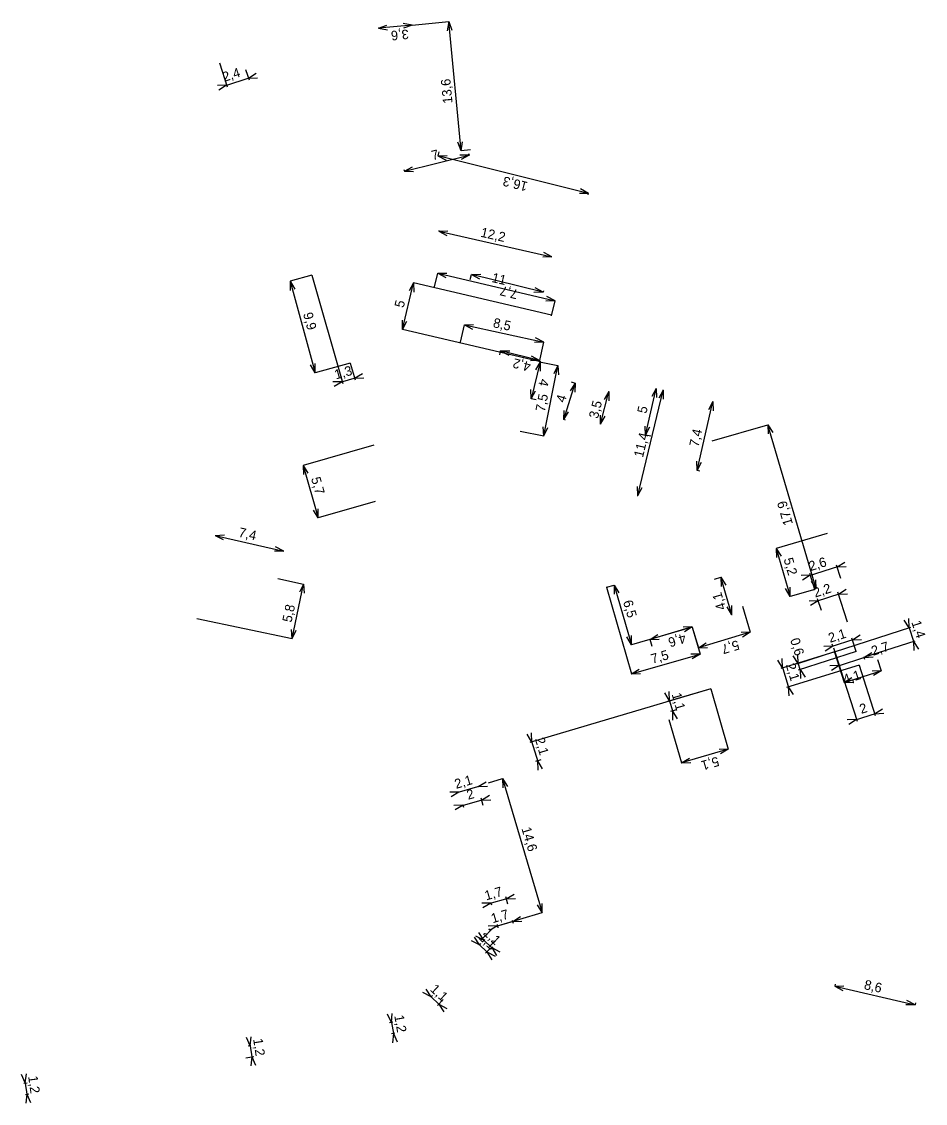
# Model space of a CAD drawing. Extents: x -743226 to -743024, y -1051383 to -1051228.
# Drawn here: x -743118.3 to -743023.7, y -1051341.7 to -1051228.4 of the extents above; entities that cross this region are included whole.
import ezdxf

# ---------------------------------------------------------------- set-up
doc = ezdxf.new("R2010")
doc.units = 0
doc.layers.add('Kota_NN', color=7, linetype='Continuous')
doc.layers.add('Kota_VN', color=7, linetype='Continuous')

msp = doc.modelspace()

# ---------------------------------------------------------------- linework, layer by layer
at = {"layer": 'Kota_NN'}
for p, q in [((-743097.59, -1051232.76), (-743096.78, -1051235.29)), ((-743094.86, -1051233.45), (-743094.5, -1051234.56)), ((-743094.56, -1051234.37), (-743093.75, -1051233.85)), ((-743096.84, -1051235.1), (-743097.8, -1051235.14)), ((-743096.84, -1051235.1), (-743097.65, -1051235.62)), ((-743097.03, -1051235.16), (-743094.37, -1051234.31)), ((-743094.56, -1051234.37), (-743093.6, -1051234.32)), ((-743078.23, -1051244.12), (-743071.47, -1051242.44)), ((-743071.47, -1051242.44), (-743072.43, -1051242.42)), ((-743071.47, -1051242.44), (-743072.31, -1051242.9)), ((-743071.52, -1051242.24), (-743071.47, -1051242.44)), ((-743078.28, -1051243.92), (-743078.23, -1051244.12)), ((-743078.23, -1051244.12), (-743077.39, -1051243.65)), ((-743078.23, -1051244.12), (-743077.27, -1051244.14)), ((-743087.92, -1051255.01), (-743090.19, -1051255.63)), ((-743087.92, -1051255.01), (-743084.69, -1051266.34)), ((-743075.07, -1051256.22), (-743074.74, -1051254.8)), ((-743074.74, -1051254.8), (-743073.78, -1051254.77)), ((-743074.74, -1051254.8), (-743062.47, -1051257.68)), ((-743074.74, -1051254.8), (-743073.89, -1051255.25)), ((-743090.19, -1051255.63), (-743087.58, -1051265.22)), ((-743090.19, -1051255.63), (-743089.71, -1051256.46)), ((-743090.19, -1051255.63), (-743090.18, -1051256.59)), ((-743078.42, -1051260.68), (-743077.28, -1051255.8)), ((-743077.28, -1051255.8), (-743077.73, -1051256.65)), ((-743062.83, -1051259.19), (-743077.28, -1051255.8)), ((-743077.28, -1051255.8), (-743077.25, -1051256.76)), ((-743062.47, -1051257.68), (-743063.43, -1051257.71)), ((-743062.47, -1051257.68), (-743063.32, -1051257.22)), ((-743062.84, -1051259.26), (-743062.47, -1051257.68)), ((-743078.42, -1051260.68), (-743078.45, -1051259.72)), ((-743078.42, -1051260.68), (-743077.97, -1051259.83)), ((-743063.97, -1051264.07), (-743078.42, -1051260.68)), ((-743072.35, -1051262.01), (-743071.96, -1051260.2)), ((-743071.96, -1051260.2), (-743071, -1051260.15)), ((-743071.96, -1051260.2), (-743063.65, -1051262.01)), ((-743071.96, -1051260.2), (-743071.11, -1051260.64)), ((-743063.65, -1051262.01), (-743064.61, -1051262.06)), ((-743063.65, -1051262.01), (-743064.5, -1051261.57)), ((-743064.1, -1051264.07), (-743063.65, -1051262.01)), ((-743087.58, -1051265.22), (-743088.06, -1051264.39)), ((-743083.9, -1051264.22), (-743087.58, -1051265.22)), ((-743087.58, -1051265.22), (-743087.58, -1051264.26)), ((-743083.9, -1051264.22), (-743083.4, -1051265.97)), ((-743064.1, -1051264.07), (-743062.16, -1051264.46)), ((-743063.64, -1051271.82), (-743062.16, -1051264.46)), ((-743062.16, -1051264.46), (-743062.58, -1051265.32)), ((-743062.16, -1051264.46), (-743062.1, -1051265.42)), ((-743084.94, -1051266.2), (-743083.26, -1051265.72)), ((-743083.45, -1051265.78), (-743082.63, -1051265.29)), ((-743083.45, -1051265.78), (-743082.49, -1051265.76)), ((-743084.75, -1051266.15), (-743085.71, -1051266.16)), ((-743084.75, -1051266.15), (-743085.57, -1051266.64)), ((-743053.8, -1051278.08), (-743051.16, -1051267.03)), ((-743051.16, -1051267.03), (-743051.62, -1051267.87)), ((-743051.23, -1051267.01), (-743051.16, -1051267.03)), ((-743051.16, -1051267.03), (-743051.14, -1051267.99)), ((-743066.12, -1051271.32), (-743063.64, -1051271.82)), ((-743063.64, -1051271.82), (-743063.7, -1051270.87)), ((-743063.64, -1051271.82), (-743063.22, -1051270.96)), ((-743081.42, -1051272.8), (-743088.82, -1051274.91)), ((-743088.82, -1051274.91), (-743087.26, -1051280.41)), ((-743088.82, -1051274.91), (-743088.33, -1051275.74)), ((-743088.82, -1051274.91), (-743088.81, -1051275.87)), ((-743053.8, -1051278.08), (-743053.83, -1051277.12)), ((-743053.87, -1051278.06), (-743053.8, -1051278.08)), ((-743053.8, -1051278.08), (-743053.34, -1051277.24)), ((-743081.28, -1051278.7), (-743087.26, -1051280.41)), ((-743087.26, -1051280.41), (-743087.75, -1051279.59)), ((-743087.26, -1051280.41), (-743087.27, -1051279.45)), ((-743098.04, -1051282.24), (-743097.08, -1051282.2)), ((-743098.04, -1051282.24), (-743098.04, -1051282.24)), ((-743098.04, -1051282.24), (-743090.87, -1051283.88)), ((-743098.04, -1051282.24), (-743097.19, -1051282.69)), ((-743033.99, -1051282.05), (-743039.31, -1051283.6)), ((-743090.87, -1051283.88), (-743091.83, -1051283.91)), ((-743090.87, -1051283.88), (-743091.72, -1051283.43)), ((-743090.87, -1051283.88), (-743090.87, -1051283.88)), ((-743039.31, -1051283.6), (-743037.84, -1051288.64)), ((-743039.31, -1051283.6), (-743038.81, -1051284.42)), ((-743039.31, -1051283.6), (-743039.28, -1051284.56)), ((-743032.94, -1051285.54), (-743032.13, -1051285.03)), ((-743035.94, -1051286.48), (-743032.75, -1051285.48)), ((-743032.56, -1051286.75), (-743033, -1051285.35)), ((-743032.94, -1051285.54), (-743031.98, -1051285.5)), ((-743091.49, -1051286.77), (-743088.79, -1051287.34)), ((-743035.75, -1051286.42), (-743036.71, -1051286.46)), ((-743035.75, -1051286.42), (-743036.56, -1051286.93)), ((-743035.29, -1051287.9), (-743035.81, -1051286.23)), ((-743089.99, -1051293.04), (-743088.79, -1051287.34)), ((-743088.79, -1051287.34), (-743089.22, -1051288.2)), ((-743088.79, -1051287.34), (-743088.74, -1051288.3)), ((-743057.08, -1051287.67), (-743056.29, -1051287.44)), ((-743057.08, -1051287.67), (-743054.47, -1051296.74)), ((-743056.29, -1051287.44), (-743054.45, -1051293.7)), ((-743056.29, -1051287.44), (-743055.79, -1051288.26)), ((-743056.29, -1051287.44), (-743056.27, -1051288.4)), ((-743037.84, -1051288.64), (-743038.34, -1051287.82)), ((-743037.84, -1051288.64), (-743037.86, -1051287.68)), ((-743035.29, -1051287.9), (-743037.84, -1051288.64)), ((-743035.11, -1051289.14), (-743032.61, -1051288.33)), ((-743031.85, -1051291.34), (-743032.86, -1051288.2)), ((-743032.8, -1051288.39), (-743031.99, -1051287.87)), ((-743032.8, -1051288.39), (-743031.84, -1051288.35)), ((-743034.92, -1051289.08), (-743035.88, -1051289.12)), ((-743034.92, -1051289.08), (-743035.72, -1051289.6)), ((-743034.59, -1051290.1), (-743034.98, -1051288.89)), ((-743099.95, -1051290.95), (-743089.99, -1051293.04)), ((-743048.11, -1051291.84), (-743054.45, -1051293.7)), ((-743048.11, -1051291.84), (-743047.29, -1051294.68)), ((-743025.41, -1051291.92), (-743025.93, -1051291.11)), ((-743025.47, -1051291.73), (-743024.89, -1051293.53)), ((-743025.41, -1051291.92), (-743025.45, -1051290.96)), ((-743089.99, -1051293.04), (-743090.04, -1051292.08)), ((-743089.99, -1051293.04), (-743089.55, -1051292.18)), ((-743054.45, -1051293.7), (-743054.95, -1051292.88)), ((-743054.45, -1051293.7), (-743054.48, -1051292.74)), ((-743033.2, -1051294.43), (-743025.22, -1051291.86)), ((-743030.96, -1051294.39), (-743031.41, -1051292.99)), ((-743031.35, -1051293.18), (-743030.54, -1051292.65)), ((-743033.39, -1051293.83), (-743034.35, -1051293.88)), ((-743033.39, -1051293.83), (-743034.2, -1051294.35)), ((-743033.58, -1051293.89), (-743031.16, -1051293.11)), ((-743033.37, -1051293.9), (-743033.45, -1051293.64)), ((-743033.33, -1051294.03), (-743030.86, -1051301.71)), ((-743031.35, -1051293.18), (-743030.39, -1051293.13)), ((-743030.13, -1051295.01), (-743024.76, -1051293.28)), ((-743024.95, -1051293.34), (-743024.43, -1051294.15)), ((-743024.95, -1051293.34), (-743024.9, -1051294.3)), ((-743054.47, -1051296.74), (-743047.29, -1051294.68)), ((-743047.29, -1051294.68), (-743048.25, -1051294.69)), ((-743047.29, -1051294.68), (-743048.12, -1051295.17)), ((-743033.18, -1051294.43), (-743038.85, -1051296.17)), ((-743038.66, -1051296.11), (-743038.69, -1051295.15)), ((-743037.02, -1051295.66), (-743037.54, -1051294.85)), ((-743033.2, -1051294.43), (-743037.21, -1051295.72)), ((-743037.02, -1051295.66), (-743037.07, -1051294.7)), ((-743030.96, -1051294.39), (-743037.01, -1051296.34)), ((-743033.25, -1051294.35), (-743032.19, -1051297.65)), ((-743033.22, -1051294.34), (-743032.67, -1051296.05)), ((-743032.92, -1051295.92), (-743029.94, -1051294.96)), ((-743030.13, -1051295.02), (-743029.32, -1051294.5)), ((-743030.13, -1051295.02), (-743029.17, -1051294.97)), ((-743030.13, -1051295.01), (-743030.07, -1051295.21)), ((-743028.7, -1051295.24), (-743028.33, -1051296.41)), ((-743054.47, -1051296.74), (-743053.65, -1051296.25)), ((-743038.66, -1051296.11), (-743039.16, -1051295.3)), ((-743038.71, -1051295.92), (-743037.99, -1051298.29)), ((-743030.64, -1051295.82), (-743038.24, -1051298.16)), ((-743037.08, -1051295.47), (-743036.76, -1051296.47)), ((-743036.82, -1051296.28), (-743036.3, -1051297.09)), ((-743036.82, -1051296.28), (-743036.77, -1051297.24)), ((-743032.73, -1051295.86), (-743033.69, -1051295.9)), ((-743032.73, -1051295.86), (-743033.54, -1051296.38)), ((-743030.65, -1051295.82), (-743028.95, -1051301.1)), ((-743054.47, -1051296.74), (-743053.51, -1051296.72)), ((-743032.19, -1051297.65), (-743028.33, -1051296.41)), ((-743032.19, -1051297.65), (-743031.39, -1051297.13)), ((-743028.33, -1051296.41), (-743029.29, -1051296.45)), ((-743028.33, -1051296.41), (-743029.14, -1051296.93)), ((-743038.05, -1051298.1), (-743037.54, -1051298.91)), ((-743038.05, -1051298.1), (-743038.01, -1051299.06)), ((-743032.19, -1051297.65), (-743031.23, -1051297.6)), ((-743031.11, -1051301.58), (-743028.83, -1051300.85)), ((-743029.02, -1051300.91), (-743028.21, -1051300.39)), ((-743029.02, -1051300.91), (-743028.06, -1051300.86)), ((-743030.92, -1051301.52), (-743031.88, -1051301.57)), ((-743030.92, -1051301.52), (-743031.73, -1051302.04)), ((-743069.42, -1051308.14), (-743067.96, -1051307.71)), ((-743067.96, -1051307.71), (-743063.81, -1051321.73)), ((-743067.96, -1051307.71), (-743067.46, -1051308.53)), ((-743067.96, -1051307.71), (-743067.94, -1051308.67)), ((-743072.72, -1051309.17), (-743070.31, -1051308.47)), ((-743070.5, -1051308.52), (-743069.68, -1051308.03)), ((-743070.5, -1051308.52), (-743069.54, -1051308.5)), ((-743070.5, -1051308.52), (-743070.5, -1051308.52)), ((-743072.53, -1051309.12), (-743073.49, -1051309.14)), ((-743072.53, -1051309.12), (-743073.35, -1051309.62)), ((-743072.53, -1051309.12), (-743072.53, -1051309.12)), ((-743063.81, -1051321.73), (-743064.31, -1051320.91)), ((-743063.81, -1051321.73), (-743063.83, -1051320.77)), ((-743068.5, -1051323.12), (-743063.81, -1051321.73)), ((-743066.89, -1051322.66), (-743066.07, -1051322.16)), ((-743068.5, -1051323.13), (-743069.46, -1051323.15)), ((-743068.5, -1051323.13), (-743069.32, -1051323.63)), ((-743068.69, -1051323.19), (-743066.7, -1051322.6)), ((-743068.54, -1051322.99), (-743068.44, -1051323.32)), ((-743066.94, -1051322.52), (-743066.84, -1051322.85)), ((-743066.89, -1051322.66), (-743065.93, -1051322.63)), ((-743069.92, -1051324.64), (-743070.77, -1051324.19)), ((-743069.92, -1051324.64), (-743070.43, -1051323.83)), ((-743070.07, -1051324.51), (-743068.95, -1051325.55)), ((-743069.83, -1051324.55), (-743070.06, -1051324.79)), ((-743069, -1051325.32), (-743069.23, -1051325.56)), ((-743069.09, -1051325.41), (-743068.24, -1051325.86)), ((-743069.09, -1051325.41), (-743068.58, -1051326.23)), ((-743033.14, -1051329.25), (-743033.19, -1051329.45)), ((-743033.19, -1051329.45), (-743032.23, -1051329.42)), ((-743033.19, -1051329.45), (-743024.78, -1051331.38)), ((-743033.19, -1051329.45), (-743032.34, -1051329.9)), ((-743024.78, -1051331.38), (-743025.74, -1051331.41)), ((-743024.78, -1051331.38), (-743025.63, -1051330.93)), ((-743024.73, -1051331.18), (-743024.78, -1051331.38)), ((-743079.59, -1051333.25), (-743079.99, -1051332.38)), ((-743079.59, -1051333.25), (-743079.5, -1051332.29)), ((-743079.44, -1051333.22), (-743079.78, -1051333.28)), ((-743079.62, -1051333.05), (-743079.35, -1051334.61)), ((-743079.23, -1051334.38), (-743079.58, -1051334.44)), ((-743079.38, -1051334.41), (-743079.47, -1051335.37)), ((-743079.38, -1051334.41), (-743078.98, -1051335.28)), ((-743117.92, -1051339.58), (-743118.3, -1051338.7)), ((-743117.95, -1051339.38), (-743117.73, -1051340.96)), ((-743117.92, -1051339.58), (-743117.8, -1051338.63)), ((-743118.07, -1051339.6), (-743117.72, -1051339.55)), ((-743117.91, -1051340.78), (-743117.56, -1051340.73)), ((-743117.76, -1051340.76), (-743117.87, -1051341.71)), ((-743117.76, -1051340.76), (-743117.38, -1051341.64))]:
    msp.add_line(p, q, dxfattribs=at)
at = {"layer": 'Kota_VN'}
for p, q in [((-743077.42, -1051228.81), (-743080.96, -1051229.15)), ((-743080.96, -1051229.15), (-743080.06, -1051228.82)), ((-743080.96, -1051229.15), (-743080.96, -1051229.15)), ((-743080.96, -1051229.15), (-743080.01, -1051229.31)), ((-743077.42, -1051228.81), (-743078.36, -1051228.66)), ((-743077.42, -1051228.81), (-743078.32, -1051229.15)), ((-743077.42, -1051228.81), (-743073.6, -1051228.45)), ((-743077.42, -1051228.81), (-743077.42, -1051228.81)), ((-743073.6, -1051228.45), (-743073.76, -1051229.4)), ((-743072.31, -1051241.99), (-743073.6, -1051228.45)), ((-743073.6, -1051228.45), (-743073.27, -1051229.35)), ((-743072.31, -1051241.99), (-743072.64, -1051241.08)), ((-743072.31, -1051241.99), (-743072.15, -1051241.04)), ((-743071.31, -1051241.89), (-743072.31, -1051241.99)), ((-743074.62, -1051242.08), (-743074.72, -1051242.49)), ((-743074.72, -1051242.49), (-743073.76, -1051242.47)), ((-743058.95, -1051246.44), (-743074.72, -1051242.49)), ((-743074.72, -1051242.49), (-743073.88, -1051242.96)), ((-743058.95, -1051246.44), (-743059.91, -1051246.45)), ((-743058.95, -1051246.44), (-743059.79, -1051245.97)), ((-743058.99, -1051246.6), (-743058.95, -1051246.44)), ((-743074.63, -1051250.32), (-743074.64, -1051250.4)), ((-743074.64, -1051250.4), (-743073.68, -1051250.36)), ((-743074.64, -1051250.4), (-743062.79, -1051253.07)), ((-743074.64, -1051250.4), (-743073.79, -1051250.84)), ((-743062.79, -1051253.07), (-743063.75, -1051253.11)), ((-743062.79, -1051253.07), (-743063.64, -1051252.62)), ((-743062.79, -1051253.07), (-743062.79, -1051253.07)), ((-743071.34, -1051255.45), (-743071.2, -1051254.92)), ((-743071.2, -1051254.92), (-743070.24, -1051254.9)), ((-743063.71, -1051256.79), (-743071.2, -1051254.92)), ((-743071.2, -1051254.92), (-743070.37, -1051255.38)), ((-743063.71, -1051256.79), (-743064.55, -1051256.32)), ((-743063.68, -1051256.65), (-743063.71, -1051256.79)), ((-743063.71, -1051256.79), (-743064.68, -1051256.81)), ((-743068.26, -1051263.34), (-743068.16, -1051262.92)), ((-743068.16, -1051262.92), (-743067.2, -1051262.91)), ((-743064.09, -1051263.94), (-743068.16, -1051262.92)), ((-743068.16, -1051262.92), (-743067.32, -1051263.39)), ((-743064.09, -1051263.94), (-743064.93, -1051263.47)), ((-743064.09, -1051263.94), (-743065.05, -1051263.95)), ((-743064.04, -1051264.08), (-743064.98, -1051267.93)), ((-743064.04, -1051264.08), (-743064.5, -1051264.92)), ((-743064.09, -1051263.93), (-743064.09, -1051263.94)), ((-743064.03, -1051264.08), (-743064.04, -1051264.08)), ((-743064.04, -1051264.08), (-743064.02, -1051265.04)), ((-743061.56, -1051270.12), (-743060.36, -1051266.29)), ((-743060.36, -1051266.29), (-743060.88, -1051267.1)), ((-743060.78, -1051266.16), (-743060.36, -1051266.29)), ((-743060.36, -1051266.29), (-743060.4, -1051267.25)), ((-743053, -1051271.75), (-743051.9, -1051266.85)), ((-743051.9, -1051266.85), (-743052.35, -1051267.71)), ((-743051.9, -1051266.85), (-743051.9, -1051266.85)), ((-743051.9, -1051266.85), (-743051.86, -1051267.81)), ((-743064.98, -1051267.93), (-743065, -1051266.97)), ((-743064.98, -1051267.93), (-743064.52, -1051267.09)), ((-743064.45, -1051268.06), (-743064.98, -1051267.93)), ((-743057.7, -1051270.6), (-743056.85, -1051267.18)), ((-743056.85, -1051267.18), (-743057.31, -1051268.02)), ((-743056.86, -1051267.18), (-743056.85, -1051267.18)), ((-743056.85, -1051267.18), (-743056.83, -1051268.14)), ((-743061.56, -1051270.12), (-743061.52, -1051269.16)), ((-743047.59, -1051275.44), (-743045.96, -1051268.23)), ((-743045.96, -1051268.23), (-743046.41, -1051269.08)), ((-743045.96, -1051268.23), (-743045.96, -1051268.23)), ((-743045.96, -1051268.23), (-743045.92, -1051269.19)), ((-743061.56, -1051270.12), (-743061.05, -1051269.31)), ((-743061.38, -1051270.18), (-743061.56, -1051270.12)), ((-743057.7, -1051270.6), (-743057.71, -1051269.64)), ((-743057.7, -1051270.6), (-743057.23, -1051269.76)), ((-743057.71, -1051270.6), (-743057.7, -1051270.6)), ((-743053, -1051271.75), (-743053.04, -1051270.79)), ((-743053, -1051271.75), (-743052.55, -1051270.89)), ((-743046.01, -1051272.36), (-743040.18, -1051270.65)), ((-743035.14, -1051287.85), (-743040.18, -1051270.65)), ((-743040.18, -1051270.65), (-743039.68, -1051271.47)), ((-743040.18, -1051270.65), (-743040.16, -1051271.61)), ((-743052.44, -1051271.87), (-743053, -1051271.75)), ((-743047.59, -1051275.44), (-743047.63, -1051274.48)), ((-743047.59, -1051275.44), (-743047.14, -1051274.59)), ((-743047.3, -1051275.51), (-743047.59, -1051275.44)), ((-743045.76, -1051286.83), (-743045.1, -1051286.63)), ((-743043.95, -1051290.56), (-743045.1, -1051286.63)), ((-743045.1, -1051286.63), (-743044.6, -1051287.45)), ((-743045.1, -1051286.63), (-743045.08, -1051287.59)), ((-743035.14, -1051287.85), (-743035.64, -1051287.03)), ((-743035.14, -1051287.85), (-743035.16, -1051286.89)), ((-743035.12, -1051287.85), (-743035.14, -1051287.85)), ((-743043.95, -1051290.56), (-743044.45, -1051289.74)), ((-743043.95, -1051290.56), (-743043.97, -1051289.6)), ((-743043.93, -1051290.56), (-743043.95, -1051290.56)), ((-743042.84, -1051289.65), (-743042.03, -1051292.38)), ((-743048.11, -1051291.83), (-743052.52, -1051293.13)), ((-743048.11, -1051291.83), (-743049.07, -1051291.86)), ((-743048.11, -1051291.83), (-743048.93, -1051292.33)), ((-743048.11, -1051291.82), (-743048.11, -1051291.83)), ((-743048.11, -1051291.84), (-743047.46, -1051294.01)), ((-743052.52, -1051293.13), (-743051.7, -1051292.63)), ((-743042.03, -1051292.38), (-743047.46, -1051294.01)), ((-743042.03, -1051292.38), (-743042.99, -1051292.41)), ((-743042.03, -1051292.38), (-743042.84, -1051292.89)), ((-743052.52, -1051293.13), (-743051.56, -1051293.11)), ((-743052.3, -1051293.86), (-743052.52, -1051293.13)), ((-743047.46, -1051294.01), (-743046.64, -1051293.51)), ((-743047.46, -1051294.01), (-743046.5, -1051293.98)), ((-743046.17, -1051298.31), (-743065.09, -1051303.94)), ((-743046.17, -1051298.31), (-743050.68, -1051299.62)), ((-743050.49, -1051299.56), (-743050.51, -1051298.6)), ((-743046.17, -1051298.31), (-743044.33, -1051304.64)), ((-743050.49, -1051299.56), (-743050.99, -1051298.74)), ((-743050.55, -1051299.37), (-743050.12, -1051300.83)), ((-743049.74, -1051300.51), (-743050.37, -1051300.69)), ((-743050.18, -1051300.64), (-743049.68, -1051301.46)), ((-743050.18, -1051300.64), (-743050.16, -1051301.6)), ((-743050.55, -1051301.51), (-743049.22, -1051306.06)), ((-743064.9, -1051303.89), (-743065.4, -1051303.07)), ((-743064.9, -1051303.89), (-743064.92, -1051302.93)), ((-743064.95, -1051303.69), (-743064.25, -1051306.04)), ((-743044.33, -1051304.64), (-743049.22, -1051306.06)), ((-743044.33, -1051304.64), (-743045.29, -1051304.66)), ((-743044.33, -1051304.64), (-743045.15, -1051305.13)), ((-743063.95, -1051305.74), (-743064.5, -1051305.91)), ((-743064.31, -1051305.85), (-743063.81, -1051306.67)), ((-743064.31, -1051305.85), (-743064.28, -1051306.81)), ((-743049.22, -1051306.06), (-743048.4, -1051305.57)), ((-743049.22, -1051306.06), (-743048.26, -1051306.04)), ((-743072.3, -1051310.55), (-743069.97, -1051309.89)), ((-743070, -1051310.53), (-743070.21, -1051309.76)), ((-743070.16, -1051309.95), (-743069.33, -1051309.46)), ((-743070.16, -1051309.95), (-743069.2, -1051309.94)), ((-743072.1, -1051310.5), (-743073.06, -1051310.51)), ((-743072.1, -1051310.5), (-743072.93, -1051310.99)), ((-743072.11, -1051310.49), (-743072.05, -1051310.69)), ((-743067.41, -1051320.86), (-743067.62, -1051320.1)), ((-743067.57, -1051320.29), (-743066.74, -1051319.8)), ((-743069.18, -1051320.75), (-743070.14, -1051320.76)), ((-743069.18, -1051320.75), (-743070.01, -1051321.24)), ((-743069.37, -1051320.8), (-743067.38, -1051320.24)), ((-743069.19, -1051320.74), (-743069.13, -1051320.94)), ((-743067.57, -1051320.29), (-743066.61, -1051320.28)), ((-743070.37, -1051325.13), (-743071.22, -1051324.68)), ((-743070.37, -1051325.13), (-743070.88, -1051324.31)), ((-743070.52, -1051324.99), (-743069.45, -1051326)), ((-743070.38, -1051325.14), (-743070.24, -1051324.99)), ((-743069.23, -1051325.47), (-743069.73, -1051326)), ((-743069.6, -1051325.86), (-743068.75, -1051326.31)), ((-743069.6, -1051325.86), (-743069.09, -1051326.67)), ((-743075.44, -1051330.56), (-743076.29, -1051330.11)), ((-743075.44, -1051330.56), (-743075.95, -1051329.74)), ((-743075.59, -1051330.42), (-743074.48, -1051331.46)), ((-743075.45, -1051330.56), (-743075.31, -1051330.41)), ((-743074.17, -1051330.83), (-743074.76, -1051331.47)), ((-743074.62, -1051331.32), (-743073.78, -1051331.77)), ((-743074.62, -1051331.32), (-743074.11, -1051332.13)), ((-743094.37, -1051335.69), (-743094.75, -1051334.81)), ((-743094.37, -1051335.69), (-743094.26, -1051334.73)), ((-743094.36, -1051335.69), (-743094.57, -1051335.72)), ((-743094.4, -1051335.49), (-743094.16, -1051337.05)), ((-743094.84, -1051336.95), (-743094, -1051336.82)), ((-743094.19, -1051336.85), (-743094.3, -1051337.8)), ((-743094.19, -1051336.85), (-743093.81, -1051337.73))]:
    msp.add_line(p, q, dxfattribs=at)

# ---------------------------------------------------------------- texts
at = {"layer": 'Kota_NN'}
for s, rotation, p in [('2,4', 17.7404, (-743097.09, -1051234.76)), ('7', 13.9362, (-743075.27, -1051242.97)), ('11', 346.7954, (-743069.16, -1051255.7)), ('5', 76.7961, (-743078.32, -1051258.47)), ('9,9', 285.2234, (-743088.85, -1051259.04)), ('8,5', 347.6724, (-743069.02, -1051260.43)), ('1,3', 15.9055, (-743085.4, -1051265.92)), ('7,5', 78.5829, (-743063.55, -1051269.36)), ('11,4', 76.5814, (-743053.27, -1051274.15)), ('5,7', 285.926, (-743088.02, -1051276.28)), ('7,4', 347.1278, (-743095.66, -1051282.37)), ('5,2', 286.2338, (-743038.56, -1051284.74)), ('2,6', 17.3378, (-743035.73, -1051285.99)), ('2,2', 17.8369, (-743035.24, -1051288.76)), ('5,8', 78.1423, (-743090.05, -1051291.41)), ('6,5', 286.3535, (-743055.36, -1051289.18)), ('1,4', 287.8385, (-743025.18, -1051291.33)), ('2,1', 17.8368, (-743033.68, -1051293.5)), ('0,6', 287.8385, (-743037.88, -1051293.17)), ('2,7', 17.8379, (-743029.18, -1051294.86)), ('7,5', 16.0531, (-743052.27, -1051295.69)), ('2,1', 287.072, (-743038.33, -1051295.8)), ('4,1', 17.8388, (-743032.15, -1051297.83)), ('2', 17.8375, (-743030.41, -1051300.94)), ('2,1', 16.2818, (-743072.82, -1051308.79)), ('14,6', 286.4968, (-743065.99, -1051312.94)), ('1,7', 16.4462, (-743069, -1051322.86)), ('1,1', 317.128, (-743070.08, -1051323.95)), ('8,6', 347.0731, (-743030.19, -1051329.73)), ('1,2', 279.9823, (-743079.3, -1051332.54)), ('1,2', 278.0226, (-743117.62, -1051338.89))]:
    msp.add_text(s, height=1, rotation=rotation, dxfattribs=at).set_placement(p)
at = {"layer": 'Kota_VN'}
for s, rotation, p in [('3,6', 185.471, (-743077.83, -1051229.26)), ('13,6', 95.4705, (-743073.19, -1051236.98)), ('16,3', 165.9302, (-743065.25, -1051245.27)), ('12,2', 347.2917, (-743070.32, -1051250.96)), ('7,7', 165.9428, (-743066.27, -1051256.56)), ('4,2', 166.0242, (-743064.93, -1051264.14)), ('4', 256.296, (-743064.04, -1051265.78)), ('4', 72.5956, (-743061.45, -1051268.41)), ('3,5', 76.0542, (-743057.98, -1051270.08)), ('5', 77.3849, (-743052.91, -1051269.54)), ('7,4', 77.2455, (-743047.46, -1051273.04)), ('17,9', 106.3318, (-743037.56, -1051281.03)), ('4,1', 106.3172, (-743044.56, -1051289.9)), ('4,6', 196.4247, (-743048.93, -1051292.49)), ('5,7', 196.6901, (-743043.36, -1051293.2)), ('1,1', 286.1455, (-743050.27, -1051298.88)), ('2,1', 286.5809, (-743064.58, -1051303.56)), ('5,1', 196.2509, (-743045.47, -1051305.39)), ('2', 15.7573, (-743071.56, -1051309.93)), ('1,7', 15.7573, (-743069.68, -1051320.47)), ('1,1', 316.8534, (-743070.56, -1051324.41)), ('1,1', 317.1146, (-743075.61, -1051329.86)), ('1,2', 278.5, (-743094.07, -1051334.98))]:
    msp.add_text(s, height=1, rotation=rotation, dxfattribs=at).set_placement(p)

doc.saveas('drawing.dxf')
